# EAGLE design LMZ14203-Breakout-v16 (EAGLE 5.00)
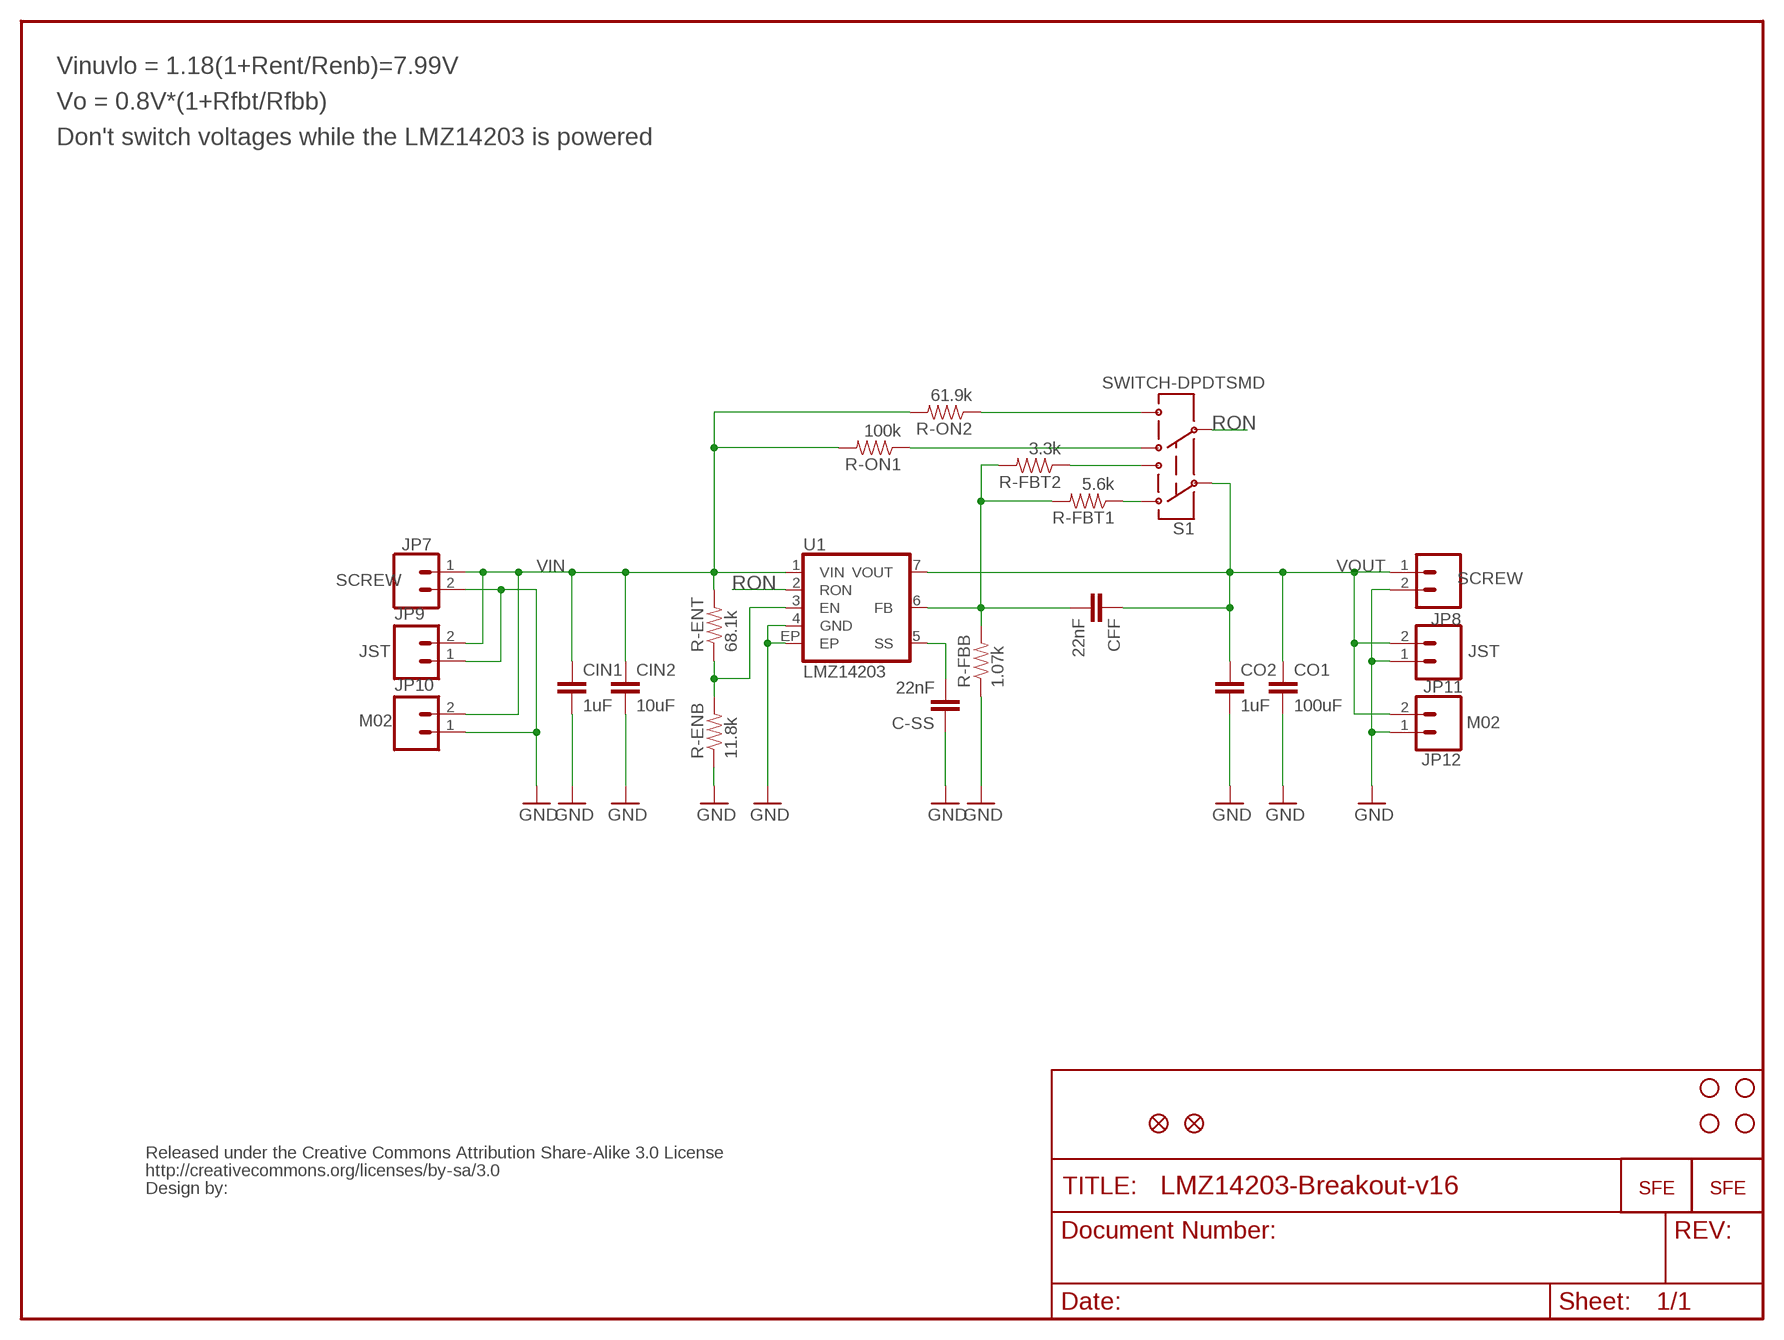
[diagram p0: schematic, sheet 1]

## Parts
C-SS  22nF  CAP0603-CAP  [0603-CAP]
CFF  22nF  CAP0603-CAP  [0603-CAP]
CIN1  1uF  CAP1206  [1206]
CIN2  10uF  CAP1210  [1210]
CO1  100uF  CAP1210  [1210]
CO2  1uF  CAP1206  [1206]
JP1  LOGO-SFESK  [SFE-LOGO-FLAME]
JP2  LOGO-SFENEW  [SFE-NEW-WEBLOGO]
JP3  STAND-OFF  [STAND-OFF]
JP4  STAND-OFF  [STAND-OFF]
JP5  STAND-OFF  [STAND-OFF]
JP6  STAND-OFF  [STAND-OFF]
JP7  SCREW  M023.5MM  [SCREWTERMINAL-3.5MM-2]
JP8  SCREW  M023.5MM  [SCREWTERMINAL-3.5MM-2]
JP9  JST  M02JST-PTH-2  [JST-2-PTH]
JP10  M02  M02PTH  [1X02]
JP11  JST  M02JST-PTH-2  [JST-2-PTH]
JP12  M02  M02PTH  [1X02]
JP13  FIDUCIAL1X2  [FIDUCIAL-1X2]
JP14  FIDUCIAL1X2  [FIDUCIAL-1X2]
R-ENB  11.8k  RESISTOR0603-RES  [0603-RES]
R-ENT  68.1k  RESISTOR0603-RES  [0603-RES]
R-FBB  1.07k  RESISTOR0603-RES  [0603-RES]
R-FBT1  5.6k  RESISTOR0603-RES  [0603-RES]
R-FBT2  3.3k  RESISTOR0603-RES  [0603-RES]
R-ON1  100k  RESISTOR0603-RES  [0603-RES]
R-ON2  61.9k  RESISTOR0603-RES  [0603-RES]
S1  SWITCH-DPDTSMD  [AYZ0202]
U1  LMZ14203  [TO-PMOD-7]
U$1  CREATIVE_COMMONS  [CREATIVE_COMMONS]

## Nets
EN: R-ENB.2 R-ENT.1 U1.3(EN)
FB: CFF.2 R-FBB.2 R-FBT1.2 R-FBT2.2 U1.6(FB)
GND: C-SS.1 CIN1.2 CIN2.2 CO1.2 CO2.2 JP7.2 JP8.2 JP9.1 JP10.1 JP11.1 JP12.1 R-ENB.1 R-FBB.1 U1.4(GND) U1.EP
RON: S1.5 U1.2(RON)
RON-3.3V: R-ON2.1 S1.6
RON-5V: R-ON1.1 S1.4
SS: C-SS.2 U1.5(SS)
VIN: CIN1.1 CIN2.1 JP7.1 JP9.2 JP10.2 R-ENT.2 R-ON1.2 R-ON2.2 U1.1(VIN)
VOUT: CFF.1 CO1.1 CO2.1 JP8.1 JP11.2 JP12.2 S1.2 U1.7(VOUT)
VOUT-3.3V: R-FBT2.1 S1.3
VOUT-5.5V: R-FBT1.1 S1.1

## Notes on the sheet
- Vinuvlo = 1.18(1+Rent/Renb)=7.99V
- Vo = 0.8V*(1+Rfbt/Rfbb)
- Don't switch voltages while the LMZ14203 is powered

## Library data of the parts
C-SS CFF CIN1 CIN2 CO1 CO2 = SparkFun:CAP: Capacitor
JP1 JP2 = SparkFun:LOGO-SFE: Spark Fun Electronics PCB Logo
JP3-JP6 = SparkFun:STAND-OFF: Stand Off
JP7-JP12 = SparkFun:M02: Header 2
JP13 JP14 = SparkFun:FIDUCIAL: Fiducial Alignment Points
R-ENB R-ENT R-FBB R-FBT1 R-FBT2 R-ON1 R-ON2 = SparkFun:RESISTOR: Resistor
S1 = SparkFun:SWITCH-DPDT: DPDT Version of the COM-00597
U1 = SparkFun:LMZ14203: LMZ14203 3A, Simple Switcher Power Module with 42V Maximum Input
U$1 = SparkFun:CREATIVE_COMMONS

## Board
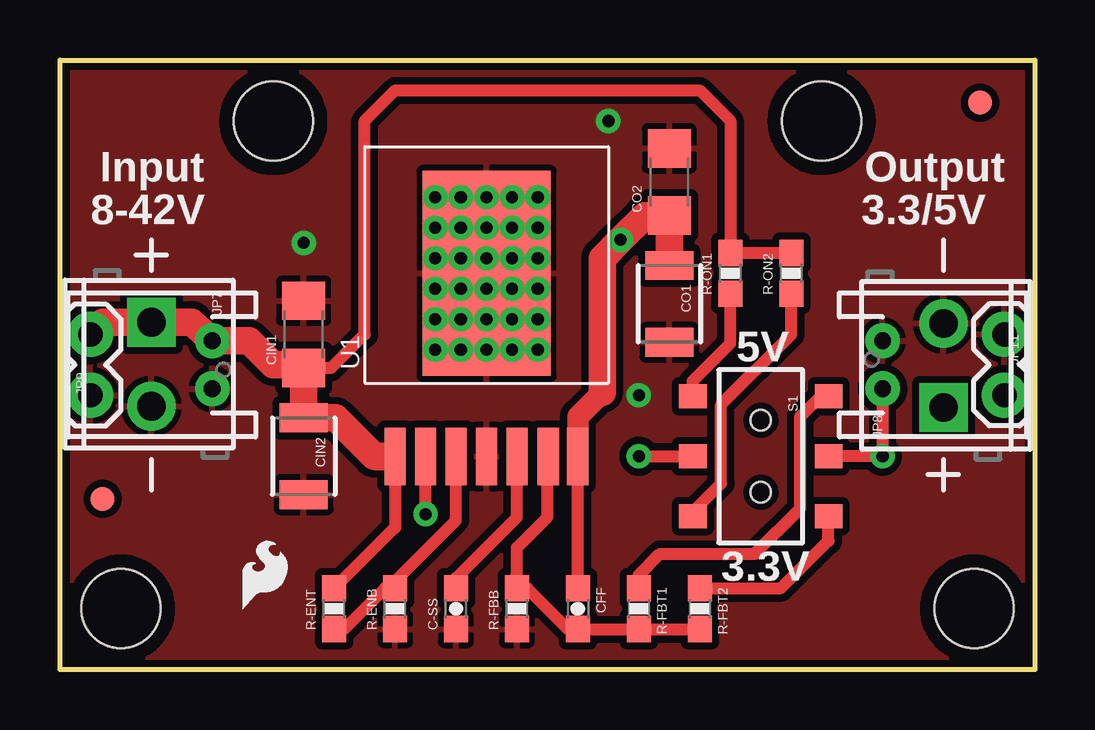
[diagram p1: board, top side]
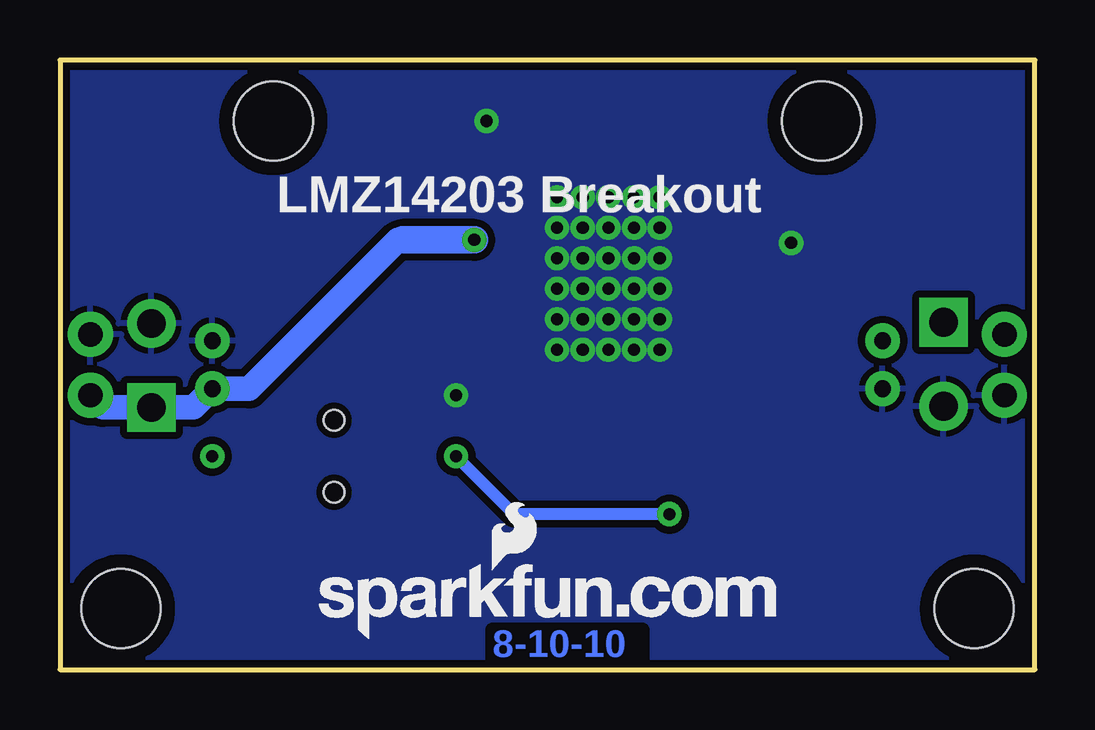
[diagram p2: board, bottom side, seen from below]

Size 40.64 x 25.4 mm. Coordinates in mm from the lower left corner, seen from the top.
Outline: 0,0 0,25.4 40.64,25.4 40.64,0 0,0
Copper layers (1*16): Top 0.035mm / dielectric 1.5mm / Bottom 0.035mm
Design rules "SparkFun": minimum track width 8mil, minimum drill 20mil, track to track 8mil, track to pad 8mil, pad to pad 8mil, via to via 8mil, smd to smd 8mil, copper to edge 9mil, drill to drill 8mil, minimum pad ring 12mil, minimum via ring 10mil, stop-mask expansion 4mil, vias tented up to drill 20mil, thermal gap 10mil

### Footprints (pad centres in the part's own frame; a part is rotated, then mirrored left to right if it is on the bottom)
0603-CAP = smd 1.1 x 1: 1 -0.85,0; 2 0.85,0
1206 = smd 1.6 x 1.8: 1 -1.4,0; 2 1.4,0
1210 = smd 1.2 x 2: 1 -1.6,0; 2 1.6,0
STAND-OFF = hole 3.302: 0,0
SCREWTERMINAL-3.5MM-2 = drill 1.2 pad 2.032 square: 1 0,0 | drill 1.2 pad 2.032 round: 2 3.5,0
JST-2-PTH = drill 0.7 pad 1.448 round: 1 -1,0; 2 1,0
1X02 = drill 1.016 pad 1.88 round: 1 0,0; 2 2.54,0
FIDUCIAL-1X2 = smd 1 x 1: 1 0,0
0603-RES = smd 1.1 x 1: 1 -0.85,0; 2 0.85,0
AYZ0202 = smd 1 x 1.15: 1 -2.5,2.825; 2 0,2.825; 3 2.5,2.825; 4 -2.5,-2.825; 5 0,-2.825; 6 2.5,-2.825 | hole 0.85: 1.5,0; -1.5,0
TO-PMOD-7 = smd 0.89 x 2.41: 1 -3.81,-7.63; 2 -2.54,-7.63; 3 -1.27,-7.63; 4 0,-7.63; 5 1.27,-7.63; 6 2.57,-7.63; 7 3.81,-7.63 | smd 5.35 x 8.54: EP 0,0

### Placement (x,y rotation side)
C-SS  16.51,2.54 90 top
CFF  21.59,2.54 270 top
CIN1  10.16,13.97 90 top
CIN2  10.16,8.89 270 top
CO1  25.4,15.24 270 top
CO2  25.4,20.32 90 top
JP1  7.62,2.54 0 top
JP2  29.84,1.27 0 bottom
JP3  2.54,2.54 0 top
JP4  38.1,2.54 0 top
JP5  8.89,22.86 0 top
JP6  31.75,22.86 0 top
JP7  3.81,14.48 270 top
JP8  36.83,10.92 90 top
JP9  6.35,12.7 90 top
JP10  1.27,11.43 90 top
JP11  34.29,12.7 270 top
JP12  39.37,13.97 270 top
JP13  1.78,7.11 0 top
JP14  38.35,23.62 0 top
R-ENB  13.97,2.54 90 top
R-ENT  11.43,2.54 90 top
R-FBB  19.05,2.54 90 top
R-FBT1  24.13,2.54 270 top
R-FBT2  26.67,2.54 270 top
R-ON1  27.94,16.51 90 top
R-ON2  30.48,16.51 90 top
S1  29.21,8.89 270 top
U1  17.78,16.51 0 top
U$1  not placed on the board

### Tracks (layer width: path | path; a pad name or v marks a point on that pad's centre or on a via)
EN
  Top 0.508: R-ENT.1 11.85,1.69 13.55,3.39 R-ENB.2 13.97,3.68 16.51,6.22 U1.3
FB
  Top 0.508: R-FBT2.2 R-FBT1.2 CFF.2 21.17,1.69 19.47,3.39 R-FBB.2 19.05,5.08 20.32,6.35 20.32,8.85 U1.6
GND  (via drill 0.51)
  other vias: 15.64,19.68 16.71,19.68 17.78,19.68 18.85,19.68 19.92,19.68 15.64,18.41 16.71,18.41 17.78,18.41 18.85,18.41 19.92,18.41 15.64,17.14 16.71,17.14 17.78,17.14 18.85,17.14 19.92,17.14 15.64,15.87 16.71,15.87 17.78,15.87 18.85,15.87 19.92,15.87 15.64,14.6 16.71,14.6 17.78,14.6 18.85,14.6 19.92,14.6 15.64,13.33 16.71,13.33 17.78,13.33 18.85,13.33 19.92,13.33 22.86,22.86 24.13,11.43 10.16,17.78
  pour Top (isolate 0.305): 0,25.4 0,0 40.64,0 40.64,25.4
  pour Bottom (isolate 0.305): 0,25.4 0,0 40.64,0 40.64,25.4
RON  (via drill 0.51)
  Top 0.508: v15.24,6.48 U1.2 | v24.13,8.89 S1.5
  Bottom 0.508: v15.24,6.48 21.72,6.48 v24.13,8.89
RON-3.3V
  Top 0.508: S1.6 26.39,6.57 27.56,7.75 27.56,11.05 30.48,13.97 R-ON2.1
RON-5V
  Top 0.508: S1.4 26.39,12.03 27.94,13.59 R-ON1.1
SS
  Top 0.508: U1.5 19.05,6.35 16.51,3.81 C-SS.2
VIN
  Top 0.508: CIN1.1 11.3,12.57 12.7,13.97 12.7,22.86 13.97,24.13 26.67,24.13 27.94,22.86 R-ON1.2 R-ON2.2 | R-ENT.2 13.97,5.93 U1.1 13.45,8.88 13.72,8.89
  Top 1.143: JP10.2 1.78,14.48 JP7.1 5.49,14.48 JP9.2 7.89,13.7 8.89,12.7 10.03,12.7 CIN1.1 CIN2.1 11.48,10.49 13.09,8.88 13.1,8.89
  Top 1.168: 13.1,8.89 13.72,8.89
VOUT  (via drill 0.51)
  Top 0.508: S1.2 v34.29,8.89 JP11.2 | CFF.1 U1.7
  Top 0.889: U1.7 21.59,10.54 22.61,11.56
  Top 1.143: 22.61,11.56 22.61,17.14 v23.37,17.91 24.38,18.92 CO2.1 CO1.1
  Bottom 1.016: 26.35,17.91 26.54,17.91 32.75,11.7 JP11.2 35.07,10.92 JP8.1 38.86,10.92 JP12.2
  Bottom 1.143: v23.37,17.91 26.35,17.91
VOUT-3.3V
  Top 0.508: R-FBT2.1 30.06,3.39 32.03,5.37 S1.3
VOUT-5.5V
  Top 0.508: S1.1 31.71,11.39 30.86,10.54 30.86,6.73 28.96,4.83 25.02,4.83 24.13,3.94 R-FBT1.1

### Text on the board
Bottom: 8-10-10
tPlace: Input | Output | 8-42V | 3.3/5V | 5V | 3.3V
bPlace: LMZ14203 Breakout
